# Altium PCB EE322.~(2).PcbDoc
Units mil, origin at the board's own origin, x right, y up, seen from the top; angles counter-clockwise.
Board outline 6000 x 4000 mil, 2 copper layers (Top Layer, Bottom Layer); 26 components, 15 nets, 57 pads, 0 vias.
Unrouted connection lines stored in the file: 42.
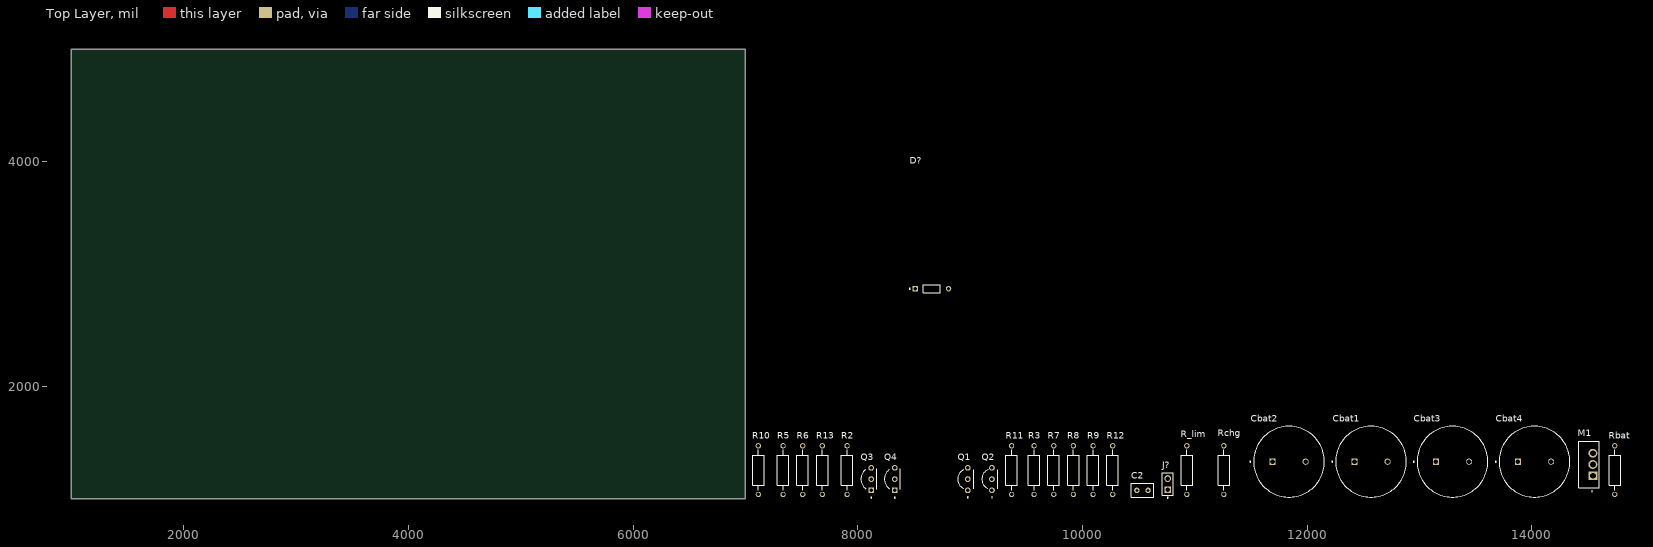
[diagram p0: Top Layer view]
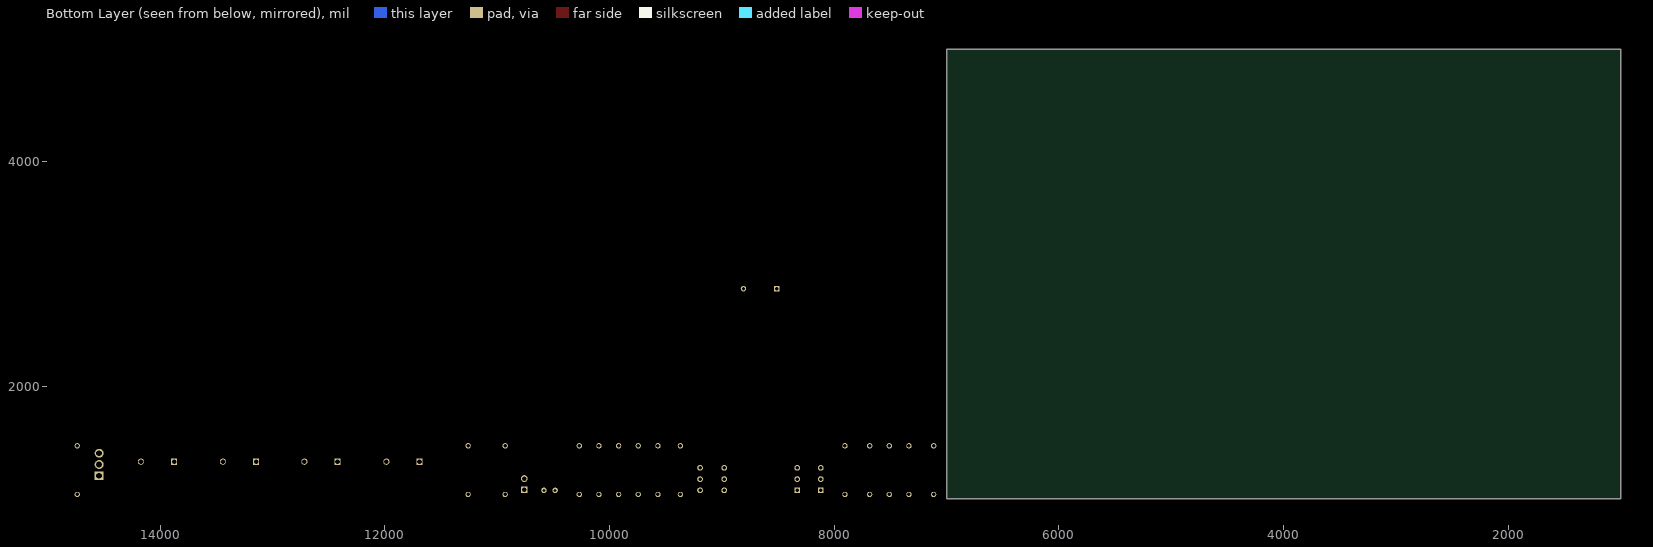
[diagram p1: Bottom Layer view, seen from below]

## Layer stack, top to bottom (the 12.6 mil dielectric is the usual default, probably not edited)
Top Solder: solder mask 0.4, Solder Resist, Dk 3.5
Top Layer: signal copper 1.4
Dielectric 1: dielectric 12.6, FR-4, Dk 4.8
Bottom Layer: signal copper 1.4
Bottom Solder: solder mask 0.4, Solder Resist, Dk 3.5

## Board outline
1000,1000 7000,1000 7000,5000 1000,5000

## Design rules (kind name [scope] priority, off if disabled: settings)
Clearance [All] p1: gap=10 ignorepadtopadclearanceinfootprint=FALSE
PolygonConnect [All] p1: connectstyle=Relief reliefconductorwidth=10 reliefentries=4 polygonreliefangle="90 Angle" airgapwidth=10
RoutingVias [All] p1: holewidth=28 width=50 viastyle="Through Hole" minholewidth=28 minwidth=50 maxholewidth=28 maxwidth=50
SolderMaskExpansion [All] p1: expansion=0 istentingtop=FALSE
Width [All] p1: maxlimit=10 minlimit=10 preferedwidth=10
30 further rules are at their usual default settings.

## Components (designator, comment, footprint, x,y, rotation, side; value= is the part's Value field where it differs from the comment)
C2 "SR291C104KAR" CAPRR254W50L508T317H508 10535,1075 r0 top
Cbat1 "ECA1HHG222" CAPPRD750W80D1600H3150 12570,1330 r0 top
Cbat2 "ECA1HHG222" CAPPRD750W80D1600H3150 11840,1330 r0 top
Cbat3 "ECA1HHG222" CAPPRD750W80D1600H3150 13295,1330 r0 top
Cbat4 "ECA1HHG222" CAPPRD750W80D1600H3150 14025,1330 r0 top
D? "1N4148" DIOAD753W49L380D172B 8660,2870 r0 top
J? "DS1021-1X2SF11-B" CONNFLY_DS1021-1X2SF11-B 10760,1130 r90 top
M1 "IRF9540" TO254P1052X465X1989-3 14545,1205 r90 top
Q1 "2N3906" TO92254P460H750-3#1 8980,1175 r90 top
Q2 "2N3906" TO92254P460H750-3#1 9195,1175 r90 top
Q3 "2N3904" TO92254P460H750-3#2 8120,1175 r90 top
Q4 "2N3904" TO92254P460H750-3#2 8330,1175 r90 top
R2 "MFR-25FBF52-10K" RESAD1100W55L680D260 7905,1255 r90 top
R3 "MFR-25FBF52-10K" RESAD1100W55L680D260 9570,1255 r90 top
R5 "MFR-25FBF52-10K" RESAD1100W55L680D260 7335,1255 r90 top
R6 "MFR-25FBF52-10K" RESAD1100W55L680D260 7510,1255 r90 top
R7 "MFR-25FBF52-10K" RESAD1100W55L680D260 9745,1255 r90 top
R8 "MFR-25FBF52-10K" RESAD1100W55L680D260 9920,1255 r90 top
R9 "MFR-25FBF52-10K" RESAD1100W55L680D260 10095,1255 r90 top
R10 "MFR-25FBF52-10K" RESAD1100W55L680D260 7115,1255 r90 top
R11 "MFR-25FBF52-10K" RESAD1100W55L680D260 9370,1255 r90 top
R12 "MFR-25FBF52-10K" RESAD1100W55L680D260 10270,1255 r90 top
R13 "MFR-25FBF52-10K" RESAD1100W55L680D260 7685,1255 r90 top
R_lim "MFR-25FBF52-10K" RESAD1100W55L680D260 10930,1255 r90 top
Rbat "MFR-25FBF52-10K" RESAD1100W55L680D260 14740,1255 r90 top
Rchg "MFR-25FBF52-10K" RESAD1100W55L680D260 11260,1255 r90 top

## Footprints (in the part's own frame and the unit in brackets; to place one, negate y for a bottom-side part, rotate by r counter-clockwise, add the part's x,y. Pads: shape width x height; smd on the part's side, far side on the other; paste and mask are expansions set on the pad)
CAPPRD750W80D1600H3150 [mm]
  round 1.4 hole 1.05: N(3.75,0)
  rect 1.4x1.4 hole 1.05: P(-3.75,0)
  silkscreen extent -8.85,-8 8,8, body extent -8,-8 8,8, height 31.5
CAPRR254W50L508T317H508 [mm]
  round 1.218 hole 0.71: 1(-1.27,0) 2(1.27,0)
  silkscreen extent -2.54,-1.59 2.54,1.59
CONNFLY_DS1021-1X2SF11-B [mm]
  rect 1.53x1.53 / inner round 1.53 / far side rect 1.53x1.53 hole 1.02 mask+0.102: 1(-1.27,0)
  round 1.53 hole 1.02 mask+0.102: 2(1.27,0)
  silkscreen extent -3.15,-1.25 2.54,1.25, body extent -2.54,-1.25 2.54,1.25, height 8.6
DIOAD753W49L380D172B [mm]
  round 1.238 hole 0.73 mask+0.102: A(3.768,0)
  rect 1.238x1.238 / inner round 1.238 / far side rect 1.238x1.238 hole 0.73 mask+0.102: K(-3.768,0)
  silkscreen extent -5.1,-0.86 1.9,0.86, body extent -0.95,-31.4 0.95,27.5, height 0.95
RESAD1100W55L680D260 [mm]
  round 1.2 hole 0.8: 1(-5.5,0) 2(5.5,0)
  silkscreen extent -4.58,-1.3 4.58,1.3, body extent -5.77,-1.2 5.77,1.2, height 2.4
TO254P1052X465X1989-3 [mm]
  rect 2.01x2.01 / inner round 2.01 / far side rect 2.01x2.01 hole 1.34: 1(0,0)
  round 2.01 hole 1.34: 2(2.54,0) 3(5.08,0)
  silkscreen extent -3.6,-1.5 7.8,3.16, body extent -5.12,-1.54 5.12,2.91, height 19.89
TO92254P460H750-3#1 [mm]
  round 1.298 hole 0.79 mask+0.102: 1(-2.54,0) 2(0,0) 3(2.54,0)
  silkscreen extent -4.22,-1.3 2.15,2.3, body extent -2.74,-1.27 2.74,2.33, height 8.09
TO92254P460H750-3#2 [mm]
  rect 1.298x1.298 / inner round 1.298 / far side rect 1.298x1.298 hole 0.79 mask+0.102: 1(-2.54,0)
  round 1.298 hole 0.79 mask+0.102: 2(0,0) 3(2.54,0)
  silkscreen extent -4.29,-1.27 2.3,2.33, body extent -2.74,-1.27 2.74,2.33, height 8.09

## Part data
C2: "SR Series 5.08 x 5.08 mm 100 nF 100 V Â±10 % Tol. X7R Radial Lead/SkyCapÂ®", Package=None
Cbat1 Cbat2 Cbat3 Cbat4: "Cap Aluminum 2200uF 50V 20% (16 X 31.5mm) Radial Aluminum Cylindrical Can 7.5mm 1470mA 2000 hr 105C Bulk", Package="RADIAL-2 Panasonic"
D?: "Diode Standard 75V 200mA Surface Mount SOD-523F", Package="AXIAL LEAD-2 ON Semiconductor"
J?: "2 position 2.54mm single row vertical pin header", Package=None
M1: "P-Channel 100 V 19A (Tc) 3.7W (Ta), 150W (Tc) Surface Mount DÂ²PAK (TO-263)", Package="TO-220-3 Vishay"
Q1 Q2: "BJT, TO-92, 40V, 200mA, PNP, 0.625W, 150Â°C", Package="TO-92 Diotec"
Q3 Q4: "BJT, TO-92, 40V, 200mA, NPN, 0.625W, 150Â°C", Package="TO-92 Diotec"
R2 R3 R5 R6 R7 R8 R9 R10 R11 R12 R13 R_lim Rbat Rchg: "10.2 kOhms Â±1% 0.25W, 1/4W Through Hole Resistor Axial - Metal Film", Package="RADIAL-2 YAGEO"

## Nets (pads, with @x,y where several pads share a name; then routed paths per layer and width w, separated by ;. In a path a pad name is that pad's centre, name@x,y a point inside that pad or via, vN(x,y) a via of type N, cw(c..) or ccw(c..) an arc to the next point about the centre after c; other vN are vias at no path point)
gnd: Cbat1.N Cbat2.N Cbat3.N Cbat4.N J?.1 R2.1 R5.1 R6.1 R10.1 R13.1 Rchg.1
NetC2_1: C2.1 D?.K M1.1 R9.2
NetC2_2: C2.2 R12.2
NetCbat1_P: Cbat1.P Cbat2.P Cbat3.P Cbat4.P Rbat.1 Rchg.2
NetD?_A: D?.A Q1.3 R5.2
NetM1_3: M1.3 Q2.1 R7.2 R8.2 R_lim.2
NetQ1_1: Q1.1 R2.2 R3.1
NetQ1_2: Q1.2 Q2.2 Q2.3 R6.2
NetQ3_1: Q3.1 Q4.1 R10.2
NetQ3_2: Q3.2 R12.1 R13.2
NetQ3_3: Q3.3 R7.1
NetQ4_2: Q4.2 R11.1
NetQ4_3: Q4.3 R8.1 R9.1
VBat: M1.2 Rbat.2
vdd: J?.2 R3.2 R11.2 R_lim.1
